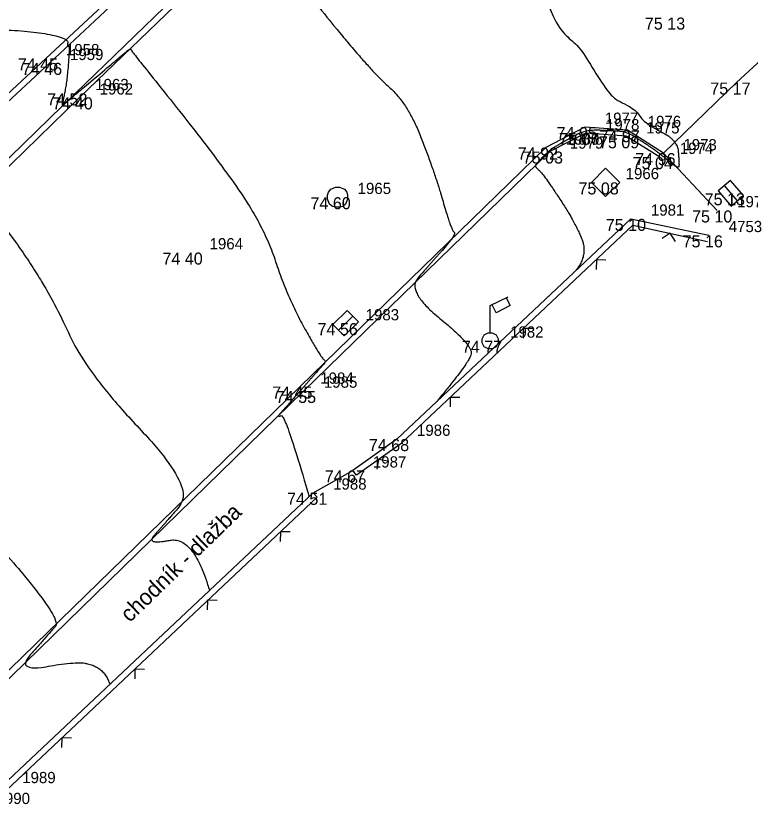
# Model space of a CAD drawing. Extents: x -704017 to -701500, y -1008977 to -1008450.
# Drawn here: x -701605.47 to -701587.16, y -1008587.05 to -1008566.93 of the extents above; entities that cross this region are included whole.
import ezdxf

# ---------------------------------------------------------------- set-up
doc = ezdxf.new("R2010")
doc.units = 0
for name, color, linetype in [('Z_body', 7, 'Continuous'), ('Z_body_cisla', 7, 'Continuous'), ('Z_body_vysky', 7, 'Continuous'), ('Z_chodnik', 7, 'Continuous'), ('Z_komunikace', 7, 'Continuous'), ('Z_obruby', 7, 'Continuous'), ('Z_oploceni', 7, 'Continuous'), ('Z_popis', 7, 'Continuous'), ('Z_rozhrani_ploch', 7, 'Continuous'), ('Z_site_znaky_kanalizace', 7, 'Continuous'), ('Z_site_znaky_nerozlisene', 7, 'Continuous'), ('Z_site_znaky_VO', 7, 'Continuous'), ('Z_vrstevnice_hlavni', 7, 'Continuous'), ('Z_vrstevnice_vedlejsi', 7, 'Continuous'), ('Z_vstupy', 7, 'Continuous')]:
    doc.layers.add(name, color=color, linetype=linetype)

# ---------------------------------------------------------------- blocks, each defined once
blk = doc.blocks.new('POINT_DISPLAY')
blk.add_line((0, 0), (0, 0))
blk = doc.blocks.new('Z212')
for p, q in [((-0.17, 0.17), (0, 0)), ((0, 0), (0.17, 0.17))]:
    blk.add_line(p, q)
blk = doc.blocks.new('Z13')
for p, q in [((0, 0.88), (0.45, 1.1)), ((0.4, 1.07), (0.5, 0.88)), ((0, 0.2), (0, 0.88)), ((0.15, 0.7), (0.05, 0.9)), ((0.5, 0.88), (0.15, 0.7)), ((-0.2, 0.05), (-0.15, 0.15)), ((-0.2, -0.05), (-0.2, 0.05)), ((-0.15, 0.15), (-0.05, 0.2)), ((-0.05, 0.2), (0.05, 0.2)), ((0.05, 0.2), (0.15, 0.15)), ((0.15, 0.15), (0.2, 0.05)), ((0.2, 0.05), (0.2, -0.05)), ((-0.15, -0.15), (-0.2, -0.05)), ((-0.05, -0.2), (-0.15, -0.15)), ((0.05, -0.2), (-0.05, -0.2)), ((0.15, -0.15), (0.05, -0.2)), ((0.2, -0.05), (0.15, -0.15))]:
    blk.add_line(p, q)
blk = doc.blocks.new('Z620')
for p, q in [((-0.17, 0.2), (-0.05, 0.25)), ((-0.05, 0.25), (0.05, 0.25)), ((0.05, 0.25), (0.17, 0.2)), ((-0.25, 0.05), (-0.23, 0.13)), ((-0.25, -0.05), (-0.25, 0.05)), ((-0.23, 0.13), (-0.17, 0.2)), ((0.17, 0.2), (0.23, 0.13)), ((0.23, 0.13), (0.25, 0.05)), ((0.25, 0.05), (0.25, -0.05)), ((-0.2, -0.17), (-0.25, -0.05)), ((-0.13, -0.23), (-0.2, -0.17)), ((0.2, -0.17), (0.13, -0.23)), ((0.25, -0.05), (0.2, -0.17)), ((-0.05, -0.25), (-0.13, -0.23)), ((0.05, -0.25), (-0.05, -0.25)), ((0.13, -0.23), (0.05, -0.25))]:
    blk.add_line(p, q)
blk = doc.blocks.new('Z38')
for p, q in [((0.25, 0.2), (-0.25, 0.2)), ((-0.25, 0.2), (-0.25, -0.2)), ((-0.25, 0), (0.25, 0)), ((0.25, -0.2), (0.25, 0.2)), ((-0.25, -0.2), (0.25, -0.2))]:
    blk.add_line(p, q)
blk = doc.blocks.new('Z608')
for p, q in [((0.25, 0.25), (-0.25, 0.25)), ((-0.25, 0.25), (-0.25, -0.25)), ((0.25, -0.25), (0.25, 0.25)), ((-0.25, -0.25), (0.25, -0.25))]:
    blk.add_line(p, q)

msp = doc.modelspace()

# ---------------------------------------------------------------- linework, layer by layer
at = {"layer": 'Z_chodnik'}
for p, q in [((-701594.51, -1008558.45), (-701604.73, -1008567.99)), ((-701604.73, -1008567.99), (-701612.22, -1008574.94))]:
    msp.add_line(p, q, dxfattribs=at)
at = {"layer": 'Z_komunikace'}
for p, q in [((-701594.03, -1008559.42), (-701603.89, -1008568.96)), ((-701603.89, -1008568.96), (-701610.44, -1008575.34)), ((-701591.3, -1008569.7), (-701592.27, -1008570.21)), ((-701590.23, -1008569.78), (-701591.3, -1008569.7)), ((-701589.34, -1008570.35), (-701590.23, -1008569.78)), ((-701592.27, -1008570.21), (-701598.39, -1008576.17)), ((-701588, -1008571.78), (-701589.34, -1008570.35)), ((-701598.39, -1008576.17), (-701609.44, -1008586.92))]:
    msp.add_line(p, q, dxfattribs=at)
at = {"layer": 'Z_obruby'}
for p, q in [((-701594.41, -1008558.51), (-701604.63, -1008568.1)), ((-701594.14, -1008559.31), (-701604, -1008568.86)), ((-701604.63, -1008568.1), (-701612.17, -1008575.07)), ((-701604, -1008568.86), (-701610.54, -1008575.23)), ((-701591.27, -1008569.85), (-701592.17, -1008570.31)), ((-701590.27, -1008569.93), (-701591.27, -1008569.85)), ((-701589.43, -1008570.45), (-701590.27, -1008569.93)), ((-701592.17, -1008570.31), (-701598.3, -1008576.28)), ((-701598.3, -1008576.28), (-701609.34, -1008587.05))]:
    msp.add_line(p, q, dxfattribs=at)
at = {"layer": 'Z_oploceni'}
for p, q in [((-701590.15, -1008571.99), (-701595.98, -1008577.48)), ((-701590.15, -1008571.99), (-701588.21, -1008572.4)), ((-701590.1, -1008572.15), (-701595.88, -1008577.6)), ((-701590.1, -1008572.15), (-701588.24, -1008572.55)), ((-701595.98, -1008577.48), (-701597.08, -1008578.26)), ((-701595.88, -1008577.6), (-701596.99, -1008578.38)), ((-701596.99, -1008578.38), (-701597.08, -1008578.26)), ((-701598.07, -1008578.82), (-701605.82, -1008586.13)), ((-701597.97, -1008578.93), (-701605.72, -1008586.24)), ((-701597.97, -1008578.93), (-701598.07, -1008578.82))]:
    msp.add_line(p, q, dxfattribs=at)
at = {"layer": 'Z_rozhrani_ploch'}
for p, q in [((-701585.93, -1008567.13), (-701587.52, -1008568.59)), ((-701587.52, -1008568.59), (-701589.34, -1008570.35))]:
    msp.add_line(p, q, dxfattribs=at)
at = {"layer": 'Z_vrstevnice_hlavni'}
for points in [[(-701600.568, -1008560.961), (-701600.058, -1008562.098), (-701598.686, -1008562.348), (-701598.69, -1008562.436), (-701598.631, -1008562.471), (-701597.966, -1008562.516), (-701598.009, -1008563.057), (-701597.461, -1008562.597), (-701596.305, -1008561.622), (-701596.234, -1008561.904), (-701595.397, -1008562.948), (-701592.812, -1008565.162), (-701591.994, -1008567.268), (-701591.417, -1008567.663), (-701590.703, -1008568.942), (-701590.027, -1008569.253), (-701589.823, -1008569.602), (-701588.993, -1008570.015), (-701588.945, -1008570.585), (-701588.957, -1008570.759), (-701589.385, -1008570.4), (-701589.626, -1008570.221), (-701590.24, -1008569.818), (-701590.542, -1008569.801), (-701591.288, -1008569.763), (-701591.844, -1008570.081), (-701592.197, -1008570.283), (-701592.492, -1008570.613), (-701592.553, -1008570.683), (-701592.342, -1008570.855), (-701591.523, -1008572.099), (-701591.214, -1008572.911), (-701591.538, -1008573.297)], [(-701613.432, -1008572.84), (-701611.831, -1008574.372), (-701611.609, -1008574.373), (-701611.613, -1008574.393), (-701611.856, -1008574.78), (-701611.953, -1008575.091), (-701611.954, -1008575.148), (-701612.033, -1008575.223), (-701612.076, -1008575.426), (-701612.03, -1008575.473), (-701611.98, -1008575.51), (-701611.77, -1008575.583), (-701611.409, -1008575.601), (-701610.954, -1008575.579), (-701610.44, -1008575.34), (-701604.24, -1008581.861), (-701604.749, -1008582.44), (-701605.529, -1008583.332), (-701603.344, -1008582.887), (-701603.137, -1008583.6)]]:
    msp.add_open_spline(points, degree=2, dxfattribs=at)
at = {"layer": 'Z_vrstevnice_vedlejsi'}
for points in [[(-701597.221, -1008557.884), (-701596.408, -1008559.698), (-701595.939, -1008559.784), (-701595.94, -1008559.814), (-701595.854, -1008559.865), (-701594.88, -1008559.93), (-701594.889, -1008560.035), (-701594.783, -1008559.946), (-701594.089, -1008559.361), (-701593.949, -1008559.163), (-701593.848, -1008559.007), (-701593.618, -1008558.489), (-701593.475, -1008558.195), (-701593.31, -1008557.768), (-701593.255, -1008557.64), (-701593.159, -1008557.386), (-701593.073, -1008557.17), (-701592.381, -1008557.835), (-701591.912, -1008558.721), (-701589.025, -1008563.687), (-701588.448, -1008564.196), (-701587.559, -1008565.754), (-701587.089, -1008566.158), (-701586.038, -1008566.778), (-701585.984, -1008566.964), (-701585.922, -1008567.107), (-701585.885, -1008567.128), (-701585.884, -1008567.194), (-701586.307, -1008567.83), (-701585.911, -1008570.368), (-701585.86, -1008570.648)], [(-701603.914, -1008564.038), (-701603.708, -1008564.498), (-701601.433, -1008564.913), (-701601.44, -1008565.058), (-701601.408, -1008565.077), (-701601.051, -1008565.101), (-701601.129, -1008566.08), (-701600.14, -1008565.248), (-701599.466, -1008564.679), (-701599.424, -1008564.844), (-701596.686, -1008568.262), (-701595.717, -1008569.092), (-701595.027, -1008570.869), (-701594.626, -1008572.278), (-701594.484, -1008572.366), (-701595.173, -1008573.139), (-701595.746, -1008573.793), (-701594.082, -1008575.144), (-701594.176, -1008575.574), (-701595.008, -1008576.565)], [(-701607.189, -1008567.056), (-701606.968, -1008567.267), (-701605.292, -1008567.275), (-701604.181, -1008567.477), (-701604.19, -1008567.68), (-701604.186, -1008567.683), (-701604.136, -1008567.686), (-701604.21, -1008568.607), (-701604.335, -1008569.187), (-701604.248, -1008569.109), (-701603.982, -1008568.877), (-701602.819, -1008567.9), (-701602.626, -1008567.737), (-701602.614, -1008567.784), (-701600.675, -1008570.205), (-701599.305, -1008572.14), (-701598.719, -1008573.93), (-701597.876, -1008575.452), (-701597.739, -1008575.536), (-701597.854, -1008575.665), (-701598.345, -1008576.225), (-701598.886, -1008576.84), (-701598.957, -1008576.921), (-701598.759, -1008576.881), (-701598.169, -1008578.914)], [(-701610.31, -1008569.948), (-701609.4, -1008570.819), (-701607.787, -1008570.827), (-701607.818, -1008570.973), (-701607.929, -1008571.149), (-701608.391, -1008572.637), (-701608.528, -1008573.27), (-701607.344, -1008572.225), (-701606.346, -1008571.353), (-701604.634, -1008573.771), (-701603.746, -1008575.801), (-701600.99, -1008578.699), (-701601.818, -1008579.64), (-701602.243, -1008580.126), (-701601.051, -1008579.884), (-701600.653, -1008581.257)]]:
    msp.add_open_spline(points, degree=2, dxfattribs=at)
at = {"layer": 'Z_vstupy'}
msp.add_line((-701598.07, -1008578.82), (-701597.08, -1008578.26), dxfattribs=at)

# ---------------------------------------------------------------- block references
at = {"layer": 'Z_body'}
for p in [(-701589.15, -1008566.97), (-701604.73, -1008567.99), (-701604.63, -1008568.1), (-701587.52, -1008568.59), (-701604, -1008568.86), (-701603.89, -1008568.96), (-701591.3, -1008569.7), (-701591.27, -1008569.85), (-701590.23, -1008569.78), (-701590.27, -1008569.93), (-701592.27, -1008570.21), (-701592.17, -1008570.31), (-701589.43, -1008570.45), (-701589.34, -1008570.35), (-701590.78, -1008571.08), (-701597.46, -1008571.45), (-701587.66, -1008571.35), (-701588, -1008571.78), (-701590.15, -1008571.99), (-701588.21, -1008572.4), (-701601.15, -1008572.83), (-701597.26, -1008574.59), (-701593.66, -1008575.03), (-701598.39, -1008576.17), (-701598.3, -1008576.28), (-701595.98, -1008577.48), (-701597.08, -1008578.26), (-701598.07, -1008578.82)]:
    msp.add_blockref('POINT_DISPLAY', p, dxfattribs=at)
at = {"layer": 'Z_oploceni'}
for p, rotation in [((-701589.17, -1008572.35), 168.1), ((-701591.01, -1008573.01), -136.70000000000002), ((-701592.83, -1008574.72), -136.70000000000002), ((-701594.65, -1008576.44), -136.70000000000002), ((-701596.44, -1008577.99), -144.70000000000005), ((-701598.88, -1008579.79), -136.70000000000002), ((-701600.7, -1008581.5), -136.70000000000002), ((-701602.51, -1008583.22), -136.70000000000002), ((-701604.33, -1008584.93), -136.70000000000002)]:
    msp.add_blockref('Z212', p, dxfattribs=dict(at, rotation=rotation))
at = {"layer": 'Z_site_znaky_kanalizace'}
for p, rotation in [((-701587.66, -1008571.35), -49.499999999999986), ((-701597.26, -1008574.59), 45)]:
    msp.add_blockref('Z38', p, dxfattribs=dict(at, rotation=rotation))
msp.add_blockref('Z620', (-701597.46, -1008571.45), dxfattribs=at)
at = {"layer": 'Z_site_znaky_nerozlisene', "rotation": -45.000000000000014}
msp.add_blockref('Z608', (-701590.78, -1008571.08), dxfattribs=at)
at = {"layer": 'Z_site_znaky_VO'}
msp.add_blockref('Z13', (-701593.66, -1008575.03), dxfattribs=at)

# ---------------------------------------------------------------- texts
at = {"layer": 'Z_body_cisla'}
for s, p in [('1958', (-701604.23, -1008567.91)), ('1959', (-701604.13, -1008568.03)), ('1963', (-701603.5, -1008568.78)), ('1962', (-701603.39, -1008568.89)), ('1977', (-701590.8, -1008569.62)), ('1978', (-701590.77, -1008569.78)), ('1976', (-701589.73, -1008569.7)), ('1975', (-701589.77, -1008569.86)), ('1980', (-701591.77, -1008570.14)), ('1979', (-701591.67, -1008570.24)), ('1974', (-701588.93, -1008570.37)), ('1973', (-701588.84, -1008570.28)), ('1966', (-701590.28, -1008571)), ('1965', (-701596.96, -1008571.37)), ('1972', (-701587.5, -1008571.7)), ('1981', (-701589.65, -1008571.91)), ('4753', (-701587.71, -1008572.32)), ('1964', (-701600.65, -1008572.75)), ('1983', (-701596.76, -1008574.52)), ('1982', (-701593.16, -1008574.95)), ('1984', (-701597.89, -1008576.1)), ('1985', (-701597.8, -1008576.2)), ('1986', (-701595.48, -1008577.4)), ('1987', (-701596.58, -1008578.19)), ('1988', (-701597.57, -1008578.74)), ('1989', (-701605.32, -1008586.06)), ('1990', (-701605.96, -1008586.58))]:
    msp.add_text(s, height=0.28, dxfattribs=at).set_placement(p)
at = {"layer": 'Z_body_vysky'}
for s, p in [('75 13', (-701589.8, -1008567.27)), ('74 45', (-701605.43, -1008568.29)), ('74 46', (-701605.33, -1008568.4)), ('75 17', (-701588.17, -1008568.89)), ('74 52', (-701604.7, -1008569.16)), ('74 40', (-701604.565, -1008569.26)), ('74 95', (-701592, -1008570)), ('75 07', (-701591.945, -1008570.15)), ('74 97', (-701590.93, -1008570.08)), ('75 09', (-701590.945, -1008570.23)), ('74 92', (-701592.97, -1008570.51)), ('75 03', (-701592.845, -1008570.61)), ('75 04', (-701590.105, -1008570.75)), ('74 96', (-701590.04, -1008570.65)), ('75 08', (-701591.455, -1008571.38)), ('74 60', (-701598.135, -1008571.75)), ('75 13', (-701588.31, -1008571.65)), ('75 10', (-701588.625, -1008572.08)), ('75 10', (-701590.775, -1008572.29)), ('75 16', (-701588.86, -1008572.7)), ('74 40', (-701601.825, -1008573.13)), ('74 56', (-701597.96, -1008574.89)), ('74 77', (-701594.36, -1008575.33)), ('74 45', (-701599.09, -1008576.47)), ('74 55', (-701599, -1008576.58)), ('74 68', (-701596.68, -1008577.78)), ('74 67', (-701597.78, -1008578.56)), ('74 51', (-701598.72, -1008579.12))]:
    msp.add_text(s, height=0.3, dxfattribs=at).set_placement(p)
at = {"layer": 'Z_popis'}
msp.add_text('chodník - dlažba', height=0.4, rotation=44.1, dxfattribs=at).set_placement((-701602.64, -1008582.07))

doc.saveas('drawing.dxf')
